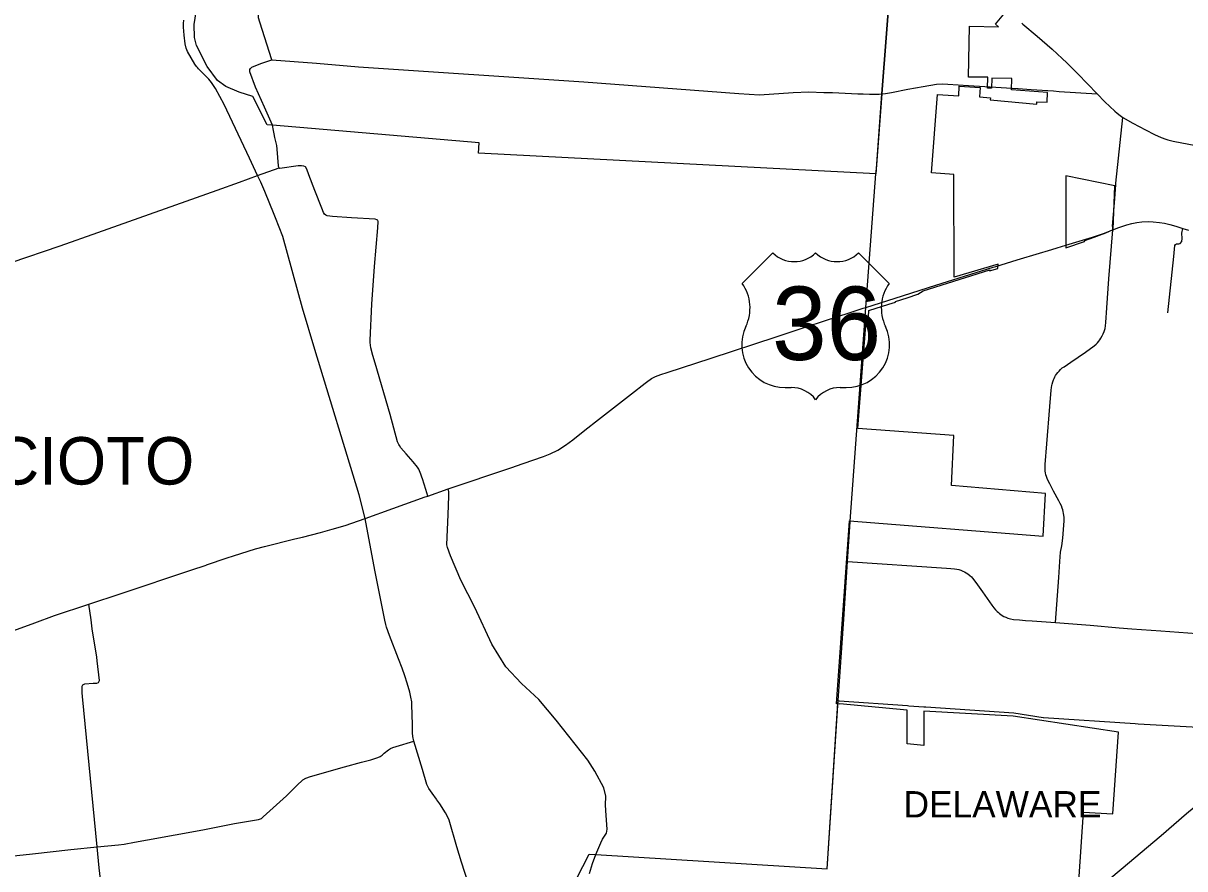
# Model space of a CAD drawing. Extents: x 1729596 to 1925846, y 659247 to 911751.
# Drawn here: x 1777664 to 1799698, y 827504 to 843541 of the extents above; entities that cross this region are included whole.
import ezdxf

# ---------------------------------------------------------------- set-up
doc = ezdxf.new("R2010")
doc.units = 0
for name, color, linetype in [('GM_X_City_Street', 7, 'Continuous'), ('GM_X_Corporation', 7, 'Continuous'), ('GM_X_Corporation_Text', 7, 'Continuous'), ('GM_X_County_Road', 7, 'Continuous'), ('GM_X_State_Route', 7, 'Continuous'), ('GM_X_Township', 7, 'Continuous'), ('GM_X_Township_Road', 7, 'Continuous'), ('GM_X_Township_Text', 7, 'Continuous'), ('GM_X_US_Route', 7, 'Continuous'), ('GM_X_US_Shield', 7, 'Continuous')]:
    doc.layers.add(name, color=color, linetype=linetype)

msp = doc.modelspace()

# ---------------------------------------------------------------- linework, layer by layer
at = {"layer": 'GM_X_City_Street'}
for points in [[(1797209, 842260), (1797313, 842248), (1798035, 842200)], [(1798391, 840480), (1798393, 840510), (1798525, 841754)], [(1797247, 832172), (1797308, 833027), (1797327, 833333), (1797341, 833506), (1797367, 833630), (1797385, 833772), (1797411, 834102), (1797410, 834129), (1797409, 834165), (1797403, 834211), (1797397, 834244), (1797390, 834277), (1797383, 834312), (1797374, 834341), (1797357, 834387), (1797336, 834430), (1797307, 834485), (1797208, 834668), (1797135, 834807), (1797094, 834887), (1797073, 834944), (1797063, 834978), (1797055, 835013), (1797051, 835044), (1797048, 835076), (1797048, 835124), (1797051, 835173), (1797082, 835564), (1797140, 836270), (1797162, 836583), (1797170, 836630), (1797176, 836667), (1797183, 836695), (1797196, 836742), (1797207, 836777), (1797219, 836804), (1797233, 836833), (1797248, 836861), (1797265, 836886), (1797288, 836914), (1797313, 836944), (1797338, 836971), (1797374, 837003), (1797407, 837026), (1797534, 837113), (1797816, 837304), (1797982, 837420), (1798018, 837451), (1798045, 837481), (1798068, 837511), (1798088, 837537), (1798108, 837569), (1798132, 837611), (1798147, 837650), (1798166, 837697), (1798185, 837753), (1798193, 837803), (1798199, 837862), (1798219, 838143), (1798256, 838693), (1798334, 839621)], [(1798334, 839621), (1798331, 839671)], [(1799374, 838047), (1799488, 839118), (1799511, 839323), (1799525, 839347), (1799540, 839354), (1799586, 839357), (1799611, 839361), (1799640, 839398), (1799646, 839456), (1799643, 839557), (1799664, 839649)], [(1793120, 830695), (1793232, 832236), (1793303, 833333), (1793351, 834085)], [(1793303, 833333), (1795175, 833207), (1795258, 833200), (1795331, 833194), (1795377, 833186), (1795411, 833177), (1795450, 833165), (1795485, 833150), (1795520, 833133), (1795550, 833116), (1795584, 833095), (1795621, 833066), (1795649, 833041), (1795673, 833015), (1795735, 832935), (1795861, 832755), (1796037, 832503), (1796074, 832453), (1796109, 832412), (1796137, 832383), (1796162, 832362), (1796185, 832343), (1796207, 832326), (1796232, 832310), (1796267, 832291), (1796301, 832276), (1796344, 832258), (1796395, 832244), (1796451, 832232), (1796564, 832223), (1796677, 832214), (1796800, 832206), (1797247, 832172), (1797901, 832125), (1798456, 832073), (1798693, 832053), (1799244, 832014), (1800095, 831955)], [(1794436, 830599), (1794466, 830597), (1794751, 830577)], [(1797010, 830375), (1797016, 830374), (1798754, 830257), (1798814, 830253), (1801541, 830101)]]:
    msp.add_lwpolyline(points, dxfattribs=at)
at = {"layer": 'GM_X_Corporation'}
msp.add_lwpolyline([(1797651, 826702), (1797775, 828578), (1798334, 828546), (1798442, 830097), (1796442, 830397), (1794748, 830490), (1794748, 829844), (1794432, 829873), (1794432, 830514), (1793153, 830634), (1793153, 830626), (1793093, 830632), (1793335, 834100), (1797009, 833813), (1797057, 834620), (1795274, 834775), (1795316, 835721), (1793499, 835852), (1793659, 837976), (1793698, 837973), (1793707, 838091), (1794085, 838213), (1794212, 838252), (1794209, 838262), (1794434, 838332), (1794637, 838403), (1794733, 838467), (1794733, 838467), (1795997, 838865), (1795996, 838844), (1796153, 838890), (1796155, 838973), (1795326, 838724), (1795319, 840669), (1794894, 840702), (1795009, 842190), (1795409, 842166), (1795420, 842348), (1795817, 842324), (1795804, 842142), (1796013, 842128), (1796009, 842085), (1796891, 842003), (1796893, 842053), (1797088, 842046), (1797094, 842227), (1796414, 842277), (1796416, 842493), (1796036, 842499), (1796033, 842307), (1795958, 842309), (1795961, 842515), (1795598, 842521), (1795613, 843484), (1796162, 843475), (1796105, 843523), (1796297, 843753)], dxfattribs=at)
msp.add_lwpolyline([(1797441, 839284), (1797798, 839399), (1797801, 839422), (1797912, 839458), (1798198, 839567), (1798339, 839626), (1798371, 840459), (1797440, 840649)], close=True, dxfattribs=at)
at = {"layer": 'GM_X_County_Road'}
for points in [[(1793847, 840780), (1793954, 842199), (1794218, 845643)], [(1782409, 841508), (1782391, 841606), (1782242, 841946), (1782072, 842331), (1781962, 842618), (1781962, 842650), (1781965, 842662), (1781975, 842683), (1782000, 842708), (1782174, 842776), (1782382, 842844), (1783229, 842784), (1784027, 842716), (1788298, 842429), (1791241, 842207), (1791633, 842186), (1792271, 842228), (1792567, 842237), (1792853, 842229), (1793017, 842224), (1793496, 842204), (1793598, 842199), (1793716, 842194), (1793856, 842196), (1793901, 842196), (1793954, 842199)], [(1793954, 842199), (1794020, 842207), (1794133, 842230), (1794444, 842288), (1794735, 842342), (1794989, 842386), (1795095, 842389), (1795206, 842386), (1795597, 842359), (1796522, 842302), (1796538, 842301)], [(1796538, 842301), (1796781, 842284), (1797209, 842260)], [(1782516, 840796), (1782504, 840822), (1782504, 840849), (1782503, 840907), (1782496, 840999), (1782473, 841224), (1782437, 841372), (1782421, 841443), (1782409, 841508)], [(1779079, 839573), (1781342, 840372), (1781765, 840527), (1782111, 840650)], [(1782111, 840650), (1782111, 840650), (1782516, 840796)], [(1793647, 838152), (1793839, 840685), (1793847, 840780)], [(1798331, 839671), (1798329, 839693), (1798369, 840209), (1798391, 840480)], [(1777434, 839004), (1778366, 839322), (1779079, 839573)], [(1793351, 834085), (1793352, 834099), (1793647, 838152)], [(1793116, 830642), (1793120, 830695)], [(1793120, 830695), (1793142, 830690), (1794436, 830599)], [(1792915, 827504), (1793116, 830642)], [(1794751, 830577), (1794787, 830575), (1796457, 830461), (1797010, 830375)], [(1776814, 827681), (1777839, 827790), (1778565, 827868), (1779067, 827919), (1779474, 827960), (1779576, 827973), (1779773, 828005), (1780019, 828053), (1781072, 828241), (1781672, 828363), (1782129, 828441), (1782181, 828458), (1782216, 828486), (1782656, 828889), (1782857, 829086), (1782966, 829190), (1783022, 829221), (1783116, 829251), (1783761, 829437), (1784081, 829523), (1784256, 829568), (1784391, 829611), (1784435, 829632), (1784475, 829661), (1784511, 829694), (1784590, 829760), (1784631, 829786), (1784675, 829805), (1784739, 829825), (1785075, 829924)]]:
    msp.add_lwpolyline(points, dxfattribs=at)
at = {"layer": 'GM_X_State_Route'}
for points in [[(1782426, 839915), (1782250, 840350), (1782172, 840527), (1782111, 840650), (1781955, 840981), (1781476, 841997), (1781310, 842306), (1781236, 842414), (1781182, 842481), (1780990, 842678), (1780970, 842699), (1780952, 842720), (1780919, 842766), (1780783, 843002), (1780756, 843068), (1780736, 843152), (1780719, 843314), (1780704, 843467), (1780704, 843535), (1780710, 843602)], [(1796609, 843541), (1796627, 843525), (1796897, 843295), (1796897, 843295)], [(1796897, 843295), (1797184, 843049), (1797375, 842873), (1797459, 842793), (1797671, 842582), (1798035, 842200), (1798181, 842051), (1798372, 841875), (1798417, 841833), (1798475, 841788), (1798525, 841754), (1798715, 841646), (1798952, 841516), (1799123, 841431), (1799251, 841372), (1799337, 841343), (1799378, 841331), (1799477, 841307), (1799775, 841246), (1800109, 841182)], [(1785512, 828810), (1785504, 828821), (1785420, 828937), (1785361, 829025), (1785323, 829103), (1785237, 829384), (1785075, 829924), (1785057, 830010), (1785050, 830079), (1785047, 830234), (1785036, 830617), (1785033, 830668), (1785019, 830761), (1784998, 830853), (1784946, 831027), (1784900, 831165), (1784850, 831306), (1784785, 831484), (1784615, 831925), (1784558, 832087), (1784544, 832136), (1784524, 832218), (1784335, 833168), (1784151, 834144), (1784039, 834594), (1783197, 837352), (1782964, 838137), (1782587, 839495), (1782452, 839852), (1782426, 839915)], [(1786229, 826847), (1785980, 827630), (1785889, 827919), (1785741, 828423), (1785715, 828492), (1785677, 828567), (1785565, 828736), (1785512, 828810)]]:
    msp.add_lwpolyline(points, dxfattribs=at)
at = {"layer": 'GM_X_Township'}
for points in [[(1794218, 845643), (1793954, 842199), (1793839, 840685), (1786300, 841075), (1786314, 841270), (1782391, 841606), (1782290, 841614), (1782021, 842150), (1781758, 842232), (1781508, 842340), (1781351, 842454), (1781155, 842721), (1780952, 843117), (1780916, 843270), (1780907, 843520), (1780980, 844003)], [(1792915, 827502), (1793120, 830695), (1793232, 832236), (1793303, 833333), (1793352, 834099), (1793647, 838152), (1793839, 840685)], [(1788160, 827310), (1788402, 827781), (1788529, 827772), (1792915, 827502)]]:
    msp.add_lwpolyline(points, dxfattribs=at)
at = {"layer": 'GM_X_Township_Road'}
for points in [[(1782382, 842844), (1782151, 843564), (1782126, 843641), (1782122, 844417), (1782128, 844831), (1782131, 844863), (1782135, 844894), (1782148, 844956), (1782159, 844992), (1782295, 845310), (1782307, 845335), (1782325, 845387), (1782332, 845413), (1782342, 845467), (1782359, 845678), (1782380, 846027), (1782397, 846217), (1782411, 846275), (1782467, 846475)], [(1785341, 834572), (1785304, 834696), (1785235, 834898), (1785228, 834929), (1785208, 834991), (1785183, 835051), (1785168, 835080), (1785144, 835122), (1785062, 835221), (1784931, 835371), (1784829, 835487), (1784800, 835530), (1784787, 835552), (1784776, 835576), (1784765, 835603), (1784625, 836119), (1784338, 837095), (1784296, 837239), (1784255, 837382), (1784244, 837484), (1784244, 837528), (1784276, 838215), (1784330, 838924), (1784391, 839658), (1784395, 839783), (1784389, 839805), (1784374, 839815), (1784341, 839823), (1783889, 839850), (1783530, 839873), (1783431, 839887), (1783405, 839902), (1783381, 839921), (1783363, 839952), (1783330, 840034), (1783198, 840371), (1783084, 840668), (1783045, 840772), (1783019, 840816), (1782989, 840831), (1782941, 840838), (1782879, 840837), (1782530, 840785), (1782516, 840796)], [(1788621, 827994), (1788650, 828063), (1788726, 828178), (1788739, 828252), (1788721, 828512), (1788707, 828711), (1788718, 828879), (1788680, 829037), (1788510, 829354), (1788376, 829562), (1787776, 830325), (1787442, 830711), (1787118, 831016), (1786817, 831334), (1786550, 831763), (1786230, 832458), (1785968, 832975), (1785767, 833439), (1785710, 833597), (1785701, 833646), (1785722, 834226), (1785735, 834569), (1785736, 834651), (1785723, 834708)], [(1779744, 821999), (1779714, 822265), (1779706, 822335), (1779104, 827522), (1779067, 827919), (1778790, 830773), (1778783, 830840), (1778783, 830969), (1778793, 830993), (1778833, 831011), (1778991, 831022), (1779061, 831027), (1779089, 831037), (1779109, 831077), (1779069, 831445), (1779061, 831516), (1778972, 832053), (1778950, 832222), (1778909, 832522)], [(1788405, 827412), (1788461, 827606), (1788529, 827772), (1788621, 827994)]]:
    msp.add_lwpolyline(points, dxfattribs=at)
at = {"layer": 'GM_X_US_Route'}
for points in [[(1798334, 839621), (1798449, 839665), (1798596, 839716), (1798693, 839742), (1798786, 839760), (1798883, 839772), (1799014, 839778), (1799098, 839777), (1799221, 839764), (1799313, 839748), (1799413, 839724), (1799529, 839690), (1799664, 839649), (1799768, 839617)], [(1797279, 839280), (1797440, 839329), (1797949, 839483), (1798026, 839508), (1798154, 839553), (1798334, 839621)], [(1797177, 839250), (1797279, 839280)], [(1796115, 838930), (1796520, 839053)], [(1796520, 839053), (1796580, 839071), (1797177, 839250)], [(1794201, 838327), (1794977, 838574), (1796065, 838914)], [(1796065, 838914), (1796113, 838930), (1796115, 838930)], [(1793596, 838135), (1793647, 838152), (1794201, 838327)], [(1785291, 834555), (1785341, 834572), (1785723, 834708), (1786913, 835110), (1787149, 835192), (1787535, 835324), (1787660, 835373), (1787802, 835441), (1787953, 835536), (1788092, 835640), (1788316, 835821), (1788577, 836027), (1789200, 836511), (1789464, 836715), (1789512, 836752), (1789559, 836786), (1789581, 836800), (1789608, 836815), (1789657, 836839), (1789708, 836860), (1789760, 836879), (1789880, 836917), (1790713, 837188), (1791944, 837592), (1792535, 837787), (1793152, 837991), (1793294, 838037)], [(1793294, 838037), (1793503, 838105), (1793596, 838135)], [(1784151, 834144), (1784673, 834334), (1785291, 834555)], [(1781140, 833266), (1781530, 833400), (1781652, 833441), (1782073, 833569), (1782240, 833615), (1782816, 833759), (1782964, 833793), (1783306, 833880), (1783524, 833942), (1783770, 834017), (1784151, 834144)], [(1773271, 830397), (1773379, 830444), (1774387, 830877), (1775615, 831340), (1776007, 831488), (1777883, 832171), (1778258, 832305), (1778909, 832522), (1779520, 832725), (1780843, 833166), (1781136, 833265), (1781140, 833266)], [(1797621, 826760), (1797666, 826798), (1798064, 827135), (1798491, 827497), (1799248, 828136), (1799732, 828551), (1800024, 828792), (1800425, 829142)]]:
    msp.add_lwpolyline(points, dxfattribs=at)
at = {"layer": 'GM_X_US_Shield'}
for p, q in [((1791884, 839184), (1791304, 838604)), ((1791884, 839184), (1791304, 838604)), ((1794088, 838604), (1793508, 839184)), ((1794088, 838604), (1793508, 839184)), ((1792116, 836632), (1792232, 836632)), ((1792116, 836632), (1792232, 836632)), ((1793160, 836632), (1793276, 836632)), ((1793160, 836632), (1793276, 836632))]:
    msp.add_line(p, q, dxfattribs=at)
for centre, radius, start, end in [((1792290, 839599), 580, 225.573, 314.427), ((1792290, 839599), 580, 225.573, 314.427), ((1793102, 839599), 580, 225.573, 314.427), ((1793102, 839599), 580, 225.573, 314.427), ((1790639, 838139), 812, 334.5471, 35.0009), ((1790639, 838139), 812, 334.5471, 35.0009), ((1794753, 838139), 812, 144.9991, 205.4529), ((1794753, 838139), 812, 144.9991, 205.4529), ((1792107, 837444), 812, 154.8319, 270.6383), ((1792107, 837444), 812, 154.8319, 270.6383), ((1793285, 837444), 812, 269.3617, 25.1681), ((1793285, 837444), 812, 269.3617, 25.1681), ((1792232, 836052), 580, 36.8699, 90), ((1792232, 836052), 580, 36.8699, 90), ((1793160, 836052), 580, 90, 143.1301), ((1793160, 836052), 580, 90, 143.1301)]:
    msp.add_arc(centre, radius, start, end, dxfattribs=at)

# ---------------------------------------------------------------- texts
at = {"layer": 'GM_X_Corporation_Text'}
msp.add_text('DELAWARE', height=500, rotation=0, dxfattribs=at).set_placement((1794364, 828476))
at = {"layer": 'GM_X_Township_Text'}
msp.add_text('SCIOTO', height=900, rotation=0, dxfattribs=at).set_placement((1776295, 834791))
at = {"layer": 'GM_X_US_Shield'}
msp.add_text('36', height=1392.2, dxfattribs=at).set_placement((1791868, 837154))
msp.add_text('36', height=1392.2, dxfattribs=at).set_placement((1791868, 837154))

doc.saveas('drawing.dxf')
